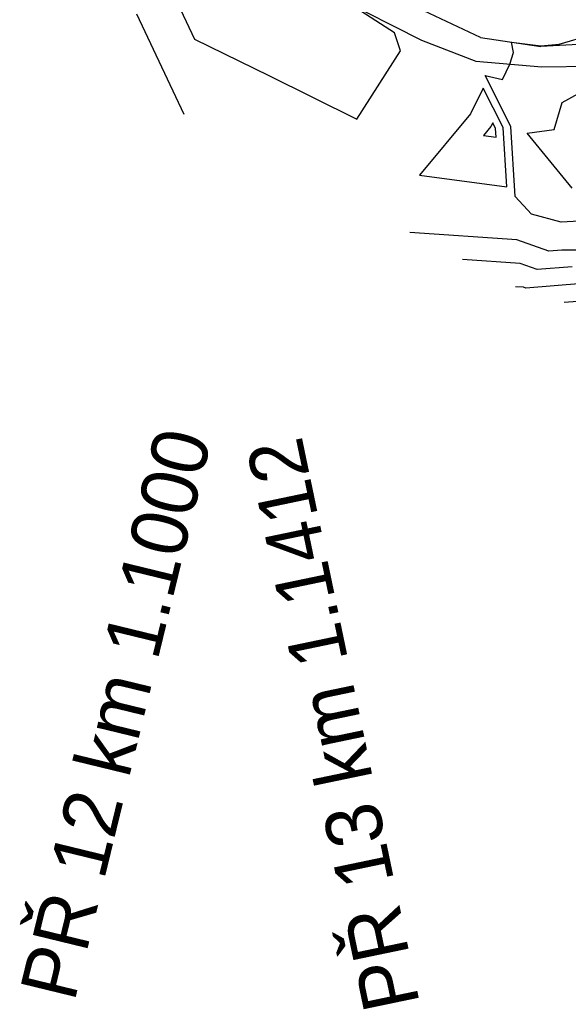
# Model space of a CAD drawing. Extents: x -549394 to -546608, y -1037055 to -1033629.
# Drawn here: x -548429.2 to -548340.9, y -1035702.6 to -1035543.3 of the extents above; entities that cross this region are included whole.
import ezdxf

# ---------------------------------------------------------------- set-up
doc = ezdxf.new("R2010")
doc.units = 0
for name, color, linetype in [('hlavni_vrst', 7, 'Continuous'), ('hrana_L', 7, 'Continuous'), ('norm_vrst', 7, 'Continuous'), ('x_popis_pricne_rezy_C1', 7, 'Continuous')]:
    doc.layers.add(name, color=color, linetype=linetype)

msp = doc.modelspace()

# ---------------------------------------------------------------- linework, layer by layer
at = {"layer": 'hlavni_vrst'}
for p, q in [((-548410.46, -1035542.31), (-548402.83, -1035558.47)), ((-548342.4, -1035547.19), (-548331.75, -1035544.15)), ((-548350.03, -1035546.89), (-548345.35, -1035547.47)), ((-548349.72, -1035548.58), (-548350.03, -1035546.89)), ((-548345.35, -1035547.47), (-548342.4, -1035547.19)), ((-548350.35, -1035550.42), (-548349.72, -1035548.58)), ((-548351.52, -1035552.93), (-548350.35, -1035550.42)), ((-548354.31, -1035552.27), (-548351.52, -1035552.93)), ((-548350.18, -1035560.47), (-548354.31, -1035552.27)), ((-548349.47, -1035571.75), (-548350.18, -1035560.47)), ((-548346.83, -1035574.57), (-548349.47, -1035571.75)), ((-548342.05, -1035575.9), (-548346.83, -1035574.57)), ((-548334.51, -1035575.4), (-548342.05, -1035575.9))]:
    msp.add_line(p, q, dxfattribs=at)
at = {"layer": 'hrana_L'}
for p, q in [((-548355.05, -1035546.14), (-548399.35, -1035525.24)), ((-548401.33, -1035527.85), (-548364.53, -1035546.59)), ((-548364.53, -1035546.59), (-548355.78, -1035549.93)), ((-548355.05, -1035546.14), (-548345.31, -1035547.6)), ((-548331.23, -1035546.79), (-548345.31, -1035547.6)), ((-548355.78, -1035549.93), (-548345.16, -1035550.89)), ((-548345.16, -1035550.89), (-548332.34, -1035550.7))]:
    msp.add_line(p, q, dxfattribs=at)
at = {"layer": 'norm_vrst'}
for p, q in [((-548406.21, -1035535.58), (-548401.1, -1035546.42)), ((-548368.87, -1035545.38), (-548376.58, -1035540.45)), ((-548401.1, -1035546.42), (-548389.12, -1035552.27)), ((-548367.93, -1035548.31), (-548368.87, -1035545.38)), ((-548374.94, -1035559.31), (-548367.93, -1035548.31)), ((-548389.12, -1035552.27), (-548374.94, -1035559.31)), ((-548354.6, -1035554.29), (-548356.65, -1035558.44)), ((-548351.39, -1035560.63), (-548354.6, -1035554.29)), ((-548341.9, -1035556.62), (-548339.28, -1035555.15)), ((-548343.19, -1035560.97), (-548341.9, -1035556.62)), ((-548356.65, -1035558.44), (-548364.89, -1035568.3)), ((-548353.38, -1035560.47), (-548354.57, -1035561.91)), ((-548353.08, -1035559.87), (-548353.38, -1035560.47)), ((-548352.61, -1035560.79), (-548353.08, -1035559.87)), ((-548352.53, -1035562.18), (-548352.61, -1035560.79)), ((-548350.8, -1035570.19), (-548351.39, -1035560.63)), ((-548347.53, -1035561.56), (-548343.19, -1035560.97)), ((-548354.57, -1035561.91), (-548352.53, -1035562.18)), ((-548340.31, -1035570.43), (-548347.53, -1035561.56)), ((-548364.89, -1035568.3), (-548350.8, -1035570.19)), ((-548349.18, -1035578.71), (-548366.45, -1035577.55)), ((-548344.06, -1035580.54), (-548349.18, -1035578.71)), ((-548341.97, -1035580.37), (-548344.06, -1035580.54)), ((-548328.71, -1035580.46), (-548341.97, -1035580.37)), ((-548348.67, -1035582.54), (-548357.94, -1035581.91)), ((-548345.92, -1035583.52), (-548348.67, -1035582.54)), ((-548340.29, -1035583.06), (-548345.92, -1035583.52)), ((-548348.15, -1035586.37), (-548349.43, -1035586.28)), ((-548347.77, -1035586.5), (-548348.15, -1035586.37)), ((-548338.6, -1035585.75), (-548347.77, -1035586.5)), ((-548336.91, -1035588.45), (-548341.57, -1035588.83))]:
    msp.add_line(p, q, dxfattribs=at)

# ---------------------------------------------------------------- texts
at = {"layer": 'x_popis_pricne_rezy_C1'}
for s, rotation, p in [('PŘ 12 km 1.1000', 76.3202, (-548420.46, -1035701.62)), ('PŘ 13 km 1.1412', 101.7797, (-548364.79, -1035701.75))]:
    msp.add_text(s, height=9.0627, rotation=rotation, dxfattribs=at).set_placement(p)

doc.saveas('drawing.dxf')
